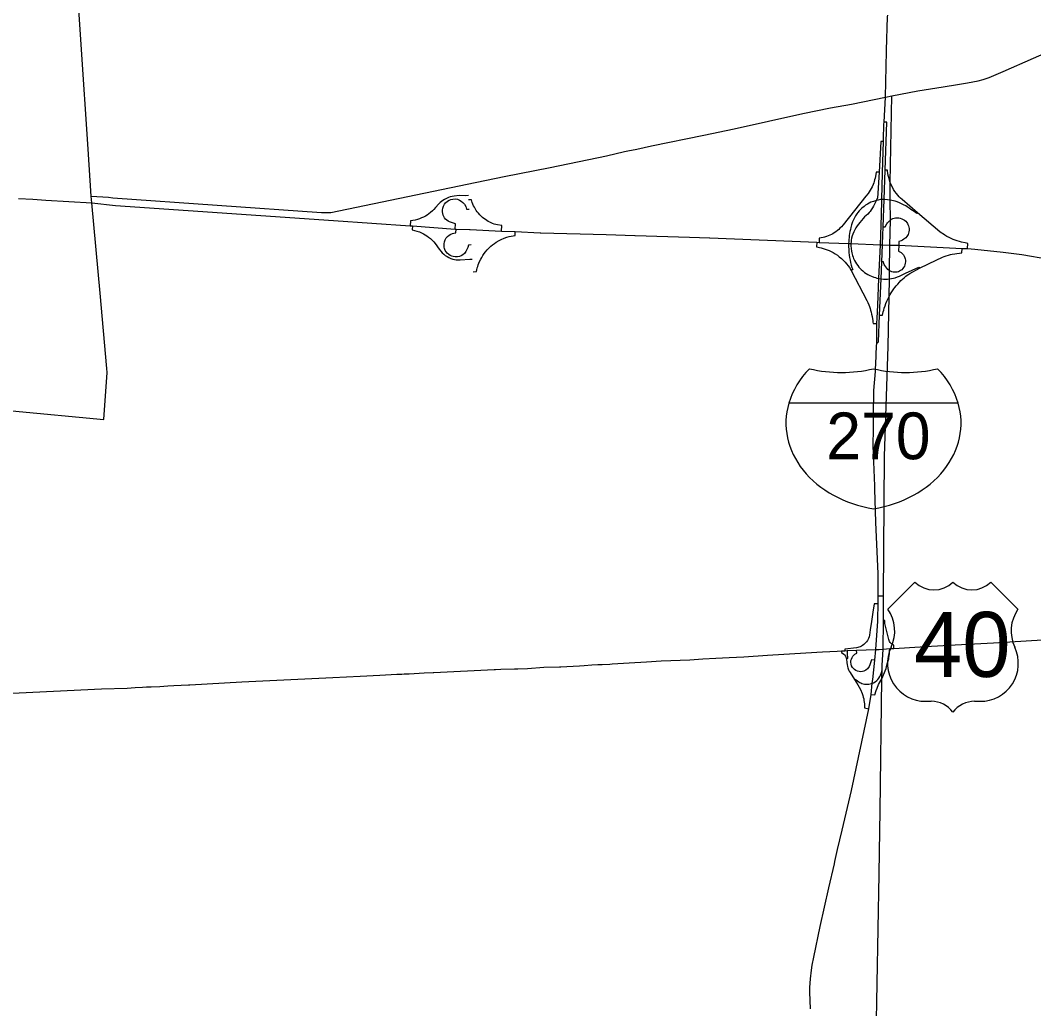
# Model space of a CAD drawing. Extents: x -1146 to -445, y -1283 to -822.
# Drawn here: x -1013.6 to -959.3, y -1085.1 to -1032.2 of the extents above; entities that cross this region are included whole.
import ezdxf

# ---------------------------------------------------------------- set-up
doc = ezdxf.new("R2010")
doc.units = 0
for name, color, linetype in [('GM_X_Interchange_Ramps', 7, 'Continuous'), ('GM_X_Interstate_Route', 7, 'Continuous'), ('GM_X_Interstate_Shield', 7, 'Continuous'), ('GM_X_Township', 7, 'Continuous'), ('GM_X_US_Route', 7, 'Continuous'), ('GM_X_US_Shield', 7, 'Continuous')]:
    doc.layers.add(name, color=color, linetype=linetype)

msp = doc.modelspace()

# ---------------------------------------------------------------- linework, layer by layer
at = {"layer": 'GM_X_Interchange_Ramps'}
for points in [[(-967.737, -1049.54), (-967.64, -1049.446), (-967.585, -1048.033), (-967.509, -1046.083), (-967.473, -1045.168), (-967.438, -1044.263), (-967.436, -1044.225), (-967.402, -1043.29), (-967.35, -1041.831), (-967.293, -1040.266), (-967.2, -1037.703), (-967.348, -1037.696)], [(-967.383, -1038.733), (-967.527, -1038.726), (-967.618, -1040.374), (-967.679, -1041.495), (-967.707, -1041.771), (-967.764, -1041.888), (-967.792, -1041.944), (-967.854, -1042.083), (-967.911, -1042.196), (-967.959, -1042.278), (-968.032, -1042.388), (-968.095, -1042.471), (-968.151, -1042.537), (-968.221, -1042.612), (-968.311, -1042.693), (-968.387, -1042.765), (-968.471, -1042.853), (-968.562, -1042.955), (-968.648, -1043.061), (-968.724, -1043.164), (-968.785, -1043.254), (-968.85, -1043.359), (-968.905, -1043.455), (-968.965, -1043.568), (-969.023, -1043.693), (-969.056, -1043.789), (-969.085, -1043.904), (-969.105, -1044.012), (-969.115, -1044.097), (-969.122, -1044.197), (-969.123, -1044.212), (-969.125, -1044.308), (-969.115, -1044.466), (-969.097, -1044.596), (-969.076, -1044.699), (-969.04, -1044.826), (-969.008, -1044.918), (-968.976, -1044.999), (-968.927, -1045.102), (-968.874, -1045.198), (-968.821, -1045.282), (-968.755, -1045.376), (-968.689, -1045.457), (-968.629, -1045.524), (-968.565, -1045.587), (-968.488, -1045.656), (-968.389, -1045.735), (-968.305, -1045.792), (-968.211, -1045.85), (-968.116, -1045.9), (-968.017, -1045.945), (-967.892, -1045.992), (-967.808, -1046.018), (-967.73, -1046.038), (-967.629, -1046.063), (-967.619, -1046.064), (-967.509, -1046.083), (-967.5, -1046.085), (-967.379, -1046.097), (-967.284, -1046.1), (-967.171, -1046.098), (-967.053, -1046.087), (-966.942, -1046.07), (-966.848, -1046.049), (-966.748, -1046.021), (-966.63, -1045.98), (-966.517, -1045.931), (-966.197, -1045.78), (-965.48, -1045.449), (-965.448, -1045.511)], [(-962.877, -1044.465), (-962.856, -1044.187), (-963.003, -1044.161), (-963.197, -1044.111), (-963.317, -1044.081), (-963.434, -1044.047), (-963.547, -1044.009), (-963.649, -1043.97), (-963.764, -1043.921), (-963.865, -1043.873), (-963.989, -1043.808), (-964.102, -1043.742), (-964.221, -1043.664), (-964.295, -1043.612), (-964.361, -1043.563), (-965.554, -1042.542), (-966.371, -1041.843), (-966.466, -1041.756), (-966.538, -1041.685), (-966.617, -1041.598), (-966.684, -1041.516), (-966.768, -1041.402), (-966.838, -1041.293), (-966.9, -1041.184), (-966.964, -1041.055), (-967.018, -1040.922), (-967.059, -1040.803), (-967.1, -1040.663), (-967.129, -1040.547), (-967.152, -1040.427), (-967.168, -1040.317), (-967.171, -1040.271), (-967.293, -1040.266)], [(-967.618, -1040.374), (-967.771, -1040.367), (-967.813, -1040.607), (-967.831, -1040.692), (-967.854, -1040.781), (-967.879, -1040.865), (-967.903, -1040.939), (-967.938, -1041.03), (-967.99, -1041.15), (-968.042, -1041.253), (-968.092, -1041.343), (-968.142, -1041.423), (-968.203, -1041.512), (-968.315, -1041.656), (-969.543, -1043.199), (-969.627, -1043.295), (-969.706, -1043.376), (-969.77, -1043.435), (-969.848, -1043.5), (-969.925, -1043.558), (-970.013, -1043.617), (-970.096, -1043.667), (-970.167, -1043.705), (-970.245, -1043.742), (-970.342, -1043.783), (-970.42, -1043.812), (-970.526, -1043.845), (-970.613, -1043.867), (-970.812, -1043.908), (-970.826, -1044.129)], [(-989.595, -1041.623), (-989.735, -1041.632), (-990.093, -1041.625), (-990.359, -1041.651), (-990.463, -1041.674), (-990.576, -1041.701), (-990.656, -1041.726), (-990.736, -1041.758), (-990.809, -1041.793), (-990.88, -1041.833), (-990.963, -1041.888), (-991.035, -1041.944), (-991.103, -1042.005), (-991.168, -1042.072), (-991.362, -1042.269), (-991.442, -1042.363), (-991.516, -1042.441), (-991.623, -1042.537), (-991.715, -1042.609), (-991.801, -1042.669), (-991.897, -1042.728), (-991.994, -1042.779), (-992.095, -1042.825), (-992.21, -1042.869), (-992.314, -1042.902), (-992.439, -1042.933), (-992.686, -1042.976), (-992.703, -1043.242)], [(-990.301, -1043.415), (-990.281, -1043.131), (-990.506, -1043.07), (-990.598, -1043.038), (-990.67, -1043.001), (-990.749, -1042.945), (-990.814, -1042.882), (-990.868, -1042.815), (-990.909, -1042.747), (-990.943, -1042.668), (-990.967, -1042.588), (-990.98, -1042.496), (-990.981, -1042.406), (-990.965, -1042.302), (-990.931, -1042.198), (-990.875, -1042.093), (-990.81, -1042.011), (-990.719, -1041.93), (-990.614, -1041.867), (-990.531, -1041.835), (-990.43, -1041.812), (-990.302, -1041.806), (-990.183, -1041.824), (-990.07, -1041.864), (-989.972, -1041.92), (-989.882, -1041.994), (-989.803, -1042.09), (-989.738, -1042.215), (-989.691, -1042.36), (-989.554, -1042.351)], [(-987.819, -1043.524), (-987.807, -1043.235), (-988.037, -1043.193), (-988.13, -1043.17), (-988.21, -1043.147), (-988.298, -1043.116), (-988.38, -1043.083), (-988.443, -1043.054), (-988.527, -1043.011), (-988.614, -1042.96), (-988.684, -1042.915), (-988.762, -1042.858), (-988.831, -1042.803), (-988.91, -1042.732), (-988.98, -1042.663), (-989.058, -1042.575), (-989.12, -1042.498), (-989.173, -1042.423), (-989.22, -1042.349), (-989.275, -1042.252), (-989.317, -1042.166), (-989.351, -1042.09), (-989.386, -1041.996), (-989.435, -1041.845), (-989.582, -1041.855)], [(-965.554, -1042.542), (-965.598, -1042.592), (-965.743, -1042.479), (-965.825, -1042.419), (-965.908, -1042.362), (-966.008, -1042.292), (-966.11, -1042.226), (-966.188, -1042.179), (-966.298, -1042.119), (-966.518, -1042.008), (-966.645, -1041.953), (-966.75, -1041.916), (-967.012, -1041.866), (-967.311, -1041.829), (-967.35, -1041.831), (-967.426, -1041.833), (-967.458, -1041.836), (-967.54, -1041.844), (-967.667, -1041.864), (-967.764, -1041.888), (-967.81, -1041.899), (-967.919, -1041.934), (-968.054, -1041.987), (-968.143, -1042.03), (-968.242, -1042.084), (-968.335, -1042.143), (-968.42, -1042.203), (-968.529, -1042.293), (-968.61, -1042.37), (-968.683, -1042.448), (-968.753, -1042.531), (-968.812, -1042.61), (-968.877, -1042.709), (-968.934, -1042.81), (-968.989, -1042.923), (-969.031, -1043.028), (-969.085, -1043.193), (-969.124, -1043.334), (-969.15, -1043.441), (-969.173, -1043.546), (-969.192, -1043.648), (-969.208, -1043.754), (-969.222, -1043.863), (-969.233, -1043.971), (-969.241, -1044.085), (-969.245, -1044.192), (-969.246, -1044.225), (-969.247, -1044.358), (-969.241, -1044.51), (-969.23, -1044.669), (-969.213, -1044.816), (-969.192, -1044.948), (-969.168, -1045.078), (-969.139, -1045.209), (-969.101, -1045.351), (-969.066, -1045.467), (-969.025, -1045.589), (-969.111, -1045.634)], [(-967.402, -1043.29), (-967.284, -1043.295), (-967.194, -1043.144), (-967.156, -1043.09), (-967.114, -1043.037), (-967.063, -1042.984), (-967.005, -1042.936), (-966.943, -1042.897), (-966.87, -1042.861), (-966.806, -1042.84), (-966.73, -1042.823), (-966.645, -1042.816), (-966.562, -1042.82), (-966.484, -1042.835), (-966.389, -1042.866), (-966.317, -1042.903), (-966.256, -1042.944), (-966.188, -1043.003), (-966.127, -1043.075), (-966.099, -1043.117), (-966.067, -1043.177), (-966.039, -1043.249), (-966.021, -1043.317), (-966.01, -1043.393), (-966.008, -1043.471), (-966.018, -1043.559), (-966.04, -1043.641), (-966.065, -1043.707), (-966.098, -1043.768), (-966.133, -1043.82), (-966.185, -1043.879), (-966.24, -1043.928), (-966.293, -1043.967), (-966.355, -1044.005), (-966.434, -1044.043), (-966.549, -1044.085), (-966.557, -1044.286)], [(-992.584, -1043.249), (-992.597, -1043.456), (-992.35, -1043.523), (-992.216, -1043.569), (-992.096, -1043.62), (-991.993, -1043.671), (-991.898, -1043.725), (-991.809, -1043.783), (-991.72, -1043.848), (-991.626, -1043.924), (-991.529, -1044.015), (-991.45, -1044.098), (-991.377, -1044.185), (-991.153, -1044.485), (-991.076, -1044.595), (-990.999, -1044.683), (-990.912, -1044.767), (-990.828, -1044.834), (-990.738, -1044.893), (-990.636, -1044.948), (-990.527, -1044.995), (-990.429, -1045.026), (-990.34, -1045.048), (-990.253, -1045.062), (-990.141, -1045.071), (-990.034, -1045.071), (-989.511, -1045.038), (-989.385, -1045.032)], [(-989.44, -1044.27), (-989.593, -1044.275), (-989.632, -1044.398), (-989.669, -1044.515), (-989.724, -1044.619), (-989.805, -1044.719), (-989.892, -1044.791), (-989.979, -1044.843), (-990.067, -1044.878), (-990.177, -1044.902), (-990.296, -1044.906), (-990.4, -1044.891), (-990.483, -1044.866), (-990.575, -1044.824), (-990.645, -1044.777), (-990.721, -1044.71), (-990.777, -1044.642), (-990.828, -1044.56), (-990.868, -1044.464), (-990.888, -1044.384), (-990.898, -1044.298), (-990.896, -1044.205), (-990.877, -1044.099), (-990.837, -1043.993), (-990.778, -1043.892), (-990.713, -1043.815), (-990.63, -1043.745), (-990.529, -1043.686), (-990.448, -1043.655), (-990.364, -1043.635), (-990.267, -1043.627), (-990.253, -1043.418)], [(-989.33, -1045.702), (-989.164, -1045.694), (-989.143, -1045.598), (-989.116, -1045.495), (-989.094, -1045.415), (-989.064, -1045.329), (-989.034, -1045.249), (-988.997, -1045.162), (-988.936, -1045.035), (-988.879, -1044.933), (-988.822, -1044.84), (-988.749, -1044.733), (-988.673, -1044.634), (-988.585, -1044.531), (-988.492, -1044.434), (-988.386, -1044.335), (-988.3, -1044.263), (-988.201, -1044.189), (-988.099, -1044.12), (-987.954, -1044.034), (-987.831, -1043.972), (-987.681, -1043.908), (-987.54, -1043.858), (-987.412, -1043.821), (-987.298, -1043.793), (-987.098, -1043.756), (-987.09, -1043.547)], [(-970.951, -1044.124), (-970.966, -1044.371), (-970.72, -1044.423), (-970.601, -1044.455), (-970.493, -1044.489), (-970.39, -1044.527), (-970.287, -1044.57), (-970.18, -1044.621), (-970.067, -1044.681), (-969.96, -1044.745), (-969.847, -1044.821), (-969.742, -1044.899), (-969.628, -1044.995), (-969.518, -1045.099), (-969.426, -1045.197), (-969.353, -1045.282), (-969.276, -1045.38), (-969.205, -1045.481), (-969.111, -1045.634), (-968.261, -1047.247), (-968.214, -1047.351), (-968.167, -1047.465), (-968.131, -1047.563), (-968.095, -1047.668), (-968.066, -1047.766), (-968.038, -1047.868), (-968.012, -1047.972), (-967.988, -1048.09), (-967.966, -1048.217), (-967.953, -1048.317), (-967.943, -1048.4), (-967.938, -1048.465), (-967.736, -1048.464)], [(-967.585, -1048.033), (-967.431, -1048.032), (-967.39, -1047.848), (-967.364, -1047.75), (-967.335, -1047.648), (-967.296, -1047.528), (-967.248, -1047.399), (-967.194, -1047.269), (-967.135, -1047.14), (-967.081, -1047.035), (-967.02, -1046.924), (-966.959, -1046.823), (-966.895, -1046.724), (-966.827, -1046.625), (-966.764, -1046.541), (-966.701, -1046.461), (-966.616, -1046.36), (-966.529, -1046.266), (-966.443, -1046.178), (-966.359, -1046.098), (-966.274, -1046.021), (-966.185, -1045.947), (-966.111, -1045.889), (-966.029, -1045.828), (-965.974, -1045.79), (-965.448, -1045.511), (-964.529, -1045.07), (-964.458, -1045.033), (-964.333, -1044.973), (-964.221, -1044.925), (-964.133, -1044.891), (-964.019, -1044.85), (-963.904, -1044.814), (-963.797, -1044.785), (-963.699, -1044.762), (-963.564, -1044.735), (-963.448, -1044.717), (-963.31, -1044.701), (-963.18, -1044.69), (-963.162, -1044.451)], [(-966.557, -1044.286), (-966.568, -1044.603), (-966.506, -1044.632), (-966.439, -1044.676), (-966.375, -1044.732), (-966.315, -1044.802), (-966.27, -1044.875), (-966.236, -1044.953), (-966.218, -1045.017), (-966.205, -1045.091), (-966.202, -1045.164), (-966.209, -1045.243), (-966.23, -1045.331), (-966.258, -1045.405), (-966.298, -1045.476), (-966.338, -1045.531), (-966.403, -1045.598), (-966.459, -1045.642), (-966.515, -1045.677), (-966.579, -1045.706), (-966.65, -1045.725), (-966.758, -1045.732), (-966.854, -1045.722), (-966.938, -1045.7), (-967.005, -1045.672), (-967.051, -1045.645), (-967.076, -1045.631), (-967.139, -1045.581), (-967.205, -1045.511), (-967.258, -1045.443), (-967.306, -1045.373), (-967.34, -1045.309), (-967.359, -1045.259), (-967.383, -1045.171), (-967.473, -1045.168)], [(-968.927, -1067.526), (-968.887, -1067.5), (-968.767, -1067.605), (-968.703, -1067.651), (-968.647, -1067.683), (-968.585, -1067.713), (-968.533, -1067.733), (-968.467, -1067.753), (-968.392, -1067.768), (-968.306, -1067.777), (-968.227, -1067.776), (-968.157, -1067.769), (-968.087, -1067.756), (-968.015, -1067.735), (-967.975, -1067.719), (-967.92, -1067.696), (-967.828, -1067.643), (-967.742, -1067.577), (-967.681, -1067.518), (-967.624, -1067.447), (-967.571, -1067.365), (-967.535, -1067.289), (-967.504, -1067.202), (-967.455, -1067.032), (-967.445, -1066.771), (-967.39, -1065.897), (-967.373, -1064.361), (-967.386, -1063.071), (-967.654, -1063.061)], [(-967.665, -1063.482), (-967.873, -1063.475), (-967.943, -1063.918), (-968.017, -1064.413), (-968.088, -1064.869), (-968.129, -1065.156), (-968.152, -1065.247), (-968.183, -1065.334), (-968.236, -1065.436), (-968.285, -1065.509), (-968.354, -1065.59), (-968.422, -1065.652), (-968.496, -1065.706), (-968.556, -1065.742), (-968.623, -1065.775), (-968.822, -1065.839), (-969.443, -1065.898), (-969.441, -1065.985)], [(-966.822, -1065.858), (-966.833, -1065.689), (-966.894, -1065.66), (-966.958, -1065.613), (-967.015, -1065.551), (-967.056, -1065.488), (-967.077, -1065.442), (-967.095, -1065.382), (-967.299, -1064.522), (-967.312, -1064.417), (-967.313, -1064.36), (-967.373, -1064.361)], [(-969.625, -1065.992), (-969.62, -1066.081), (-969.499, -1066.17), (-969.456, -1066.214), (-969.415, -1066.27), (-969.386, -1066.325), (-969.37, -1066.368), (-969.356, -1066.417), (-969.338, -1066.629), (-969.329, -1066.717), (-969.307, -1066.825), (-969.283, -1066.907), (-969.243, -1067.009), (-969.208, -1067.08), (-969.163, -1067.155), (-968.927, -1067.526), (-968.751, -1067.813), (-968.614, -1068.069), (-968.522, -1068.284), (-968.489, -1068.378), (-968.46, -1068.475), (-968.438, -1068.566), (-968.423, -1068.65), (-968.411, -1068.74), (-968.403, -1068.828), (-968.399, -1068.907), (-968.399, -1069.038), (-968.162, -1069.088)], [(-969.323, -1065.981), (-969.315, -1066.116), (-969.312, -1066.407), (-969.356, -1066.417)], [(-967.833, -1066.483), (-968.028, -1066.471), (-968.112, -1066.741), (-968.152, -1066.837), (-968.238, -1066.954), (-968.331, -1067.029), (-968.422, -1067.075), (-968.502, -1067.098), (-968.603, -1067.109), (-968.688, -1067.102), (-968.773, -1067.081), (-968.858, -1067.043), (-968.926, -1066.998), (-968.985, -1066.943), (-969.037, -1066.877), (-969.082, -1066.794), (-969.11, -1066.71), (-969.123, -1066.601), (-969.117, -1066.514), (-969.097, -1066.43), (-969.063, -1066.349), (-969.016, -1066.277), (-968.966, -1066.221), (-968.906, -1066.171), (-968.834, -1066.128), (-968.811, -1066.119), (-968.815, -1065.962)], [(-968.043, -1068.321), (-967.839, -1068.353), (-967.766, -1068.109), (-967.721, -1067.981), (-967.636, -1067.789), (-967.471, -1067.484), (-967.236, -1066.937), (-967.195, -1066.754), (-967.16, -1066.635), (-967.132, -1066.521), (-967.1, -1066.414), (-967.088, -1066.354), (-967.068, -1066.27), (-967.062, -1066.134), (-967.048, -1066.014), (-967.04, -1065.874)]]:
    msp.add_lwpolyline(points, dxfattribs=at)
at = {"layer": 'GM_X_Interstate_Route'}
for points in [[(-967.216, -1033.837), (-967.155, -1032.067), (-967.152, -1031.977)], [(-967.266, -1036.362), (-967.218, -1033.903), (-967.216, -1033.837)], [(-967.352, -1037.811), (-967.348, -1037.696), (-967.266, -1036.362)], [(-967.379, -1038.618), (-967.352, -1037.811)], [(-967.429, -1040.444), (-967.428, -1040.397), (-967.383, -1038.733), (-967.379, -1038.618)], [(-967.443, -1041.102), (-967.429, -1040.444)], [(-967.486, -1042.681), (-967.458, -1041.872), (-967.458, -1041.836), (-967.443, -1041.102)], [(-1013.666, -1041.775), (-1012.91, -1041.822), (-1012.206, -1041.866)], [(-1012.206, -1041.866), (-1009.745, -1042.021), (-1008.48, -1042.148), (-996.816, -1042.957)], [(-996.816, -1042.957), (-992.703, -1043.242), (-992.584, -1043.249), (-990.301, -1043.415), (-990.253, -1043.418), (-989.537, -1043.434)], [(-967.541, -1044.26), (-967.486, -1042.681)], [(-989.537, -1043.434), (-989.491, -1043.435), (-987.819, -1043.524), (-987.09, -1043.547), (-985.757, -1043.614)], [(-985.757, -1043.614), (-985.712, -1043.616), (-982.216, -1043.703), (-980.687, -1043.756)], [(-980.687, -1043.756), (-980.661, -1043.757), (-977.764, -1043.859), (-976.686, -1043.894)], [(-976.686, -1043.894), (-976.674, -1043.894), (-970.951, -1044.124), (-970.826, -1044.129), (-969.245, -1044.192), (-969.122, -1044.197), (-967.541, -1044.26)], [(-967.688, -1047.483), (-967.619, -1046.064), (-967.541, -1044.26)], [(-967.541, -1044.26), (-967.438, -1044.263), (-967.047, -1044.273), (-966.68, -1044.283)], [(-966.68, -1044.283), (-966.557, -1044.286), (-963.162, -1044.451), (-962.877, -1044.465), (-962.489, -1044.502)], [(-962.489, -1044.502), (-960.968, -1044.647), (-959.976, -1044.785), (-958.533, -1045.024), (-958.498, -1045.03)], [(-967.722, -1048.184), (-967.688, -1047.483)], [(-967.736, -1048.787), (-967.736, -1048.464), (-967.722, -1048.184)], [(-967.737, -1049.325), (-967.736, -1048.787)], [(-967.743, -1049.674), (-967.737, -1049.54), (-967.737, -1049.325)], [(-967.804, -1050.878), (-967.791, -1050.65), (-967.743, -1049.674)], [(-967.919, -1054.09), (-967.918, -1054.015), (-967.915, -1053.33), (-967.894, -1052.067), (-967.813, -1051.04), (-967.804, -1050.878)], [(-967.844, -1057.304), (-967.849, -1057.166), (-967.924, -1055.015), (-967.919, -1054.09)], [(-967.655, -1062.257), (-967.656, -1061.87), (-967.793, -1059.107), (-967.843, -1057.337), (-967.844, -1057.304)], [(-967.665, -1063.482), (-967.654, -1063.061), (-967.655, -1062.257)], [(-967.685, -1064.297), (-967.665, -1063.482)], [(-967.781, -1065.924), (-967.687, -1064.406), (-967.685, -1064.297)], [(-967.953, -1067.533), (-967.833, -1066.483), (-967.781, -1065.924)], [(-969.723, -1076.115), (-969.597, -1075.581), (-969.09, -1073.472), (-968.162, -1069.088), (-968.043, -1068.321), (-967.975, -1067.719), (-967.953, -1067.533)], [(-969.976, -1077.266), (-969.841, -1076.62), (-969.723, -1076.115)], [(-970.296, -1078.676), (-970.002, -1077.394), (-969.976, -1077.266)], [(-971.293, -1085.147), (-971.322, -1084.268), (-971.313, -1084.017), (-971.282, -1083.547), (-971.236, -1083.085), (-971.198, -1082.808), (-971.113, -1082.385), (-970.77, -1080.748), (-970.296, -1078.676)]]:
    msp.add_lwpolyline(points, dxfattribs=at)
at = {"layer": 'GM_X_Interstate_Shield'}
msp.add_line((-963.381, -1052.728), (-972.446, -1052.728), dxfattribs=at)
msp.add_line((-963.381, -1052.728), (-972.446, -1052.728), dxfattribs=at)
for centre, start_param, end_param in [((-966.741, -1053.8), 2.47259, 2.911027), ((-969.625, -1046.409), 4.415841, 5.008937), ((-966.201, -1046.409), 4.415841, 5.008937), ((-969.085, -1053.8), 0.230566, 0.669003), ((-966.741, -1053.8), 2.911027, 4.511031), ((-969.085, -1053.8), 4.913747, 6.513751)]:
    msp.add_ellipse(centre, major_axis=(5.859, 0), ratio=0.8, start_param=start_param, end_param=end_param, dxfattribs=at)
at = {"layer": 'GM_X_Township'}
for points in [[(-1009.776, -1041.652), (-1009.942, -1039.137), (-1010.312, -1033.534), (-1010.827, -1025.755), (-1011.143, -1022.204), (-1011.463, -1020.087), (-1012.848, -1007.56), (-1013.063, -1005.635), (-1013.224, -1004.12), (-1013.486, -1001.672)], [(-967.767, -1086.722), (-967.605, -1077.953), (-967.591, -1076.751), (-967.563, -1074.56), (-967.471, -1067.484), (-967.455, -1067.032), (-967.445, -1066.771), (-967.39, -1065.897), (-967.373, -1064.361), (-967.386, -1063.071), (-967.317, -1055.599), (-967.123, -1049.679), (-967.081, -1047.035), (-967.053, -1046.087), (-967.051, -1045.645), (-967.047, -1044.273), (-967.005, -1042.936), (-967.012, -1041.867), (-967.018, -1040.923), (-966.936, -1036.293), (-965.542, -1036.027), (-964.176, -1035.802), (-963.416, -1035.684), (-962.889, -1035.6), (-962.315, -1035.491), (-962.038, -1035.413), (-961.715, -1035.301), (-960.972, -1034.98), (-959.353, -1034.273), (-955.306, -1032.509)], [(-1014.013, -1053.141), (-1009.102, -1053.617), (-1008.928, -1051.091), (-1008.941, -1050.873), (-1009.307, -1046.85), (-1009.745, -1042.021), (-1009.776, -1041.652), (-1008.86, -1041.707), (-1008.625, -1041.743), (-997.463, -1042.533), (-996.959, -1042.526), (-989.657, -1041.01), (-987.682, -1040.609), (-985.221, -1040.122), (-982.207, -1039.497), (-981.246, -1039.261), (-981.058, -1039.226), (-980.58, -1039.138), (-979.789, -1038.971), (-976.987, -1038.389), (-975.378, -1038.047), (-971.69, -1037.238), (-970.21, -1036.923), (-969.081, -1036.725), (-967.266, -1036.362), (-966.936, -1036.293)]]:
    msp.add_lwpolyline(points, dxfattribs=at)
at = {"layer": 'GM_X_US_Route'}
for points in [[(-966.822, -1065.858), (-966.822, -1065.858), (-965.419, -1065.78)], [(-965.419, -1065.78), (-963.876, -1065.694)], [(-963.876, -1065.694), (-961.49, -1065.562)], [(-961.49, -1065.562), (-957.999, -1065.341)], [(-980.988, -1066.634), (-980.07, -1066.576), (-979.276, -1066.528), (-977.74, -1066.47), (-977.046, -1066.42), (-976.342, -1066.392), (-975.644, -1066.352), (-974.851, -1066.31), (-973.577, -1066.232)], [(-973.577, -1066.232), (-970.943, -1066.07), (-970.644, -1066.054)], [(-970.644, -1066.054), (-969.85, -1066.012), (-969.625, -1065.992)], [(-969.625, -1065.992), (-969.441, -1065.985), (-969.323, -1065.981), (-968.815, -1065.962), (-967.781, -1065.924)], [(-967.781, -1065.924), (-967.616, -1065.913)], [(-967.616, -1065.913), (-967.39, -1065.897), (-967.04, -1065.874)], [(-967.04, -1065.874), (-966.822, -1065.858)], [(-987.088, -1066.955), (-986.956, -1066.952), (-986.422, -1066.938), (-985.547, -1066.873), (-984.709, -1066.842), (-984.65, -1066.84), (-984.328, -1066.827), (-983.638, -1066.788), (-983.395, -1066.773), (-982.99, -1066.748), (-982.66, -1066.729), (-982.431, -1066.718)], [(-982.431, -1066.718), (-982.032, -1066.7), (-981.901, -1066.691)], [(-981.901, -1066.691), (-980.988, -1066.634)], [(-1001.711, -1067.65), (-996.84, -1067.416)], [(-996.84, -1067.416), (-995.392, -1067.347)], [(-995.392, -1067.347), (-994.339, -1067.297), (-993.417, -1067.249)], [(-993.417, -1067.249), (-993.154, -1067.235)], [(-993.154, -1067.235), (-993.022, -1067.229)], [(-993.022, -1067.229), (-992.828, -1067.219), (-992.759, -1067.215)], [(-992.759, -1067.215), (-991.969, -1067.174)], [(-991.969, -1067.174), (-991.473, -1067.15), (-991.441, -1067.148)], [(-991.441, -1067.148), (-988.21, -1066.987), (-988.144, -1066.983)], [(-988.144, -1066.983), (-987.864, -1066.969), (-987.124, -1066.956), (-987.088, -1066.955)], [(-1009.235, -1068.021), (-1007.857, -1067.988), (-1007.432, -1067.957)], [(-1007.432, -1067.957), (-1007.028, -1067.935), (-1006.823, -1067.925)], [(-1006.823, -1067.925), (-1006.564, -1067.913), (-1006.098, -1067.893), (-1005.67, -1067.867), (-1005.354, -1067.853), (-1004.579, -1067.815), (-1004.51, -1067.811)], [(-1004.51, -1067.811), (-1001.711, -1067.65)], [(-1043.371, -1069.665), (-1036.862, -1069.334), (-1028.965, -1068.995), (-1026.028, -1068.832), (-1025.848, -1068.833), (-1023.012, -1068.7), (-1021.174, -1068.604), (-1019.911, -1068.543), (-1014.37, -1068.275), (-1009.235, -1068.021)]]:
    msp.add_lwpolyline(points, dxfattribs=at)
at = {"layer": 'GM_X_US_Shield'}
for p, q in [((-965.692, -1062.313), (-967.142, -1063.763)), ((-960.181, -1063.763), (-961.631, -1062.313)), ((-965.112, -1068.694), (-964.822, -1068.694)), ((-962.501, -1068.694), (-962.211, -1068.694))]:
    msp.add_line(p, q, dxfattribs=at)
for centre, radius, start, end in [((-964.677, -1061.277), 1.45, 225.573, 314.427), ((-962.646, -1061.277), 1.45, 225.573, 314.427), ((-968.805, -1064.927), 2.03, 334.5471, 35.0009), ((-958.518, -1064.927), 2.03, 144.9991, 205.4529), ((-965.134, -1066.663), 2.03, 154.8319, 270.6383), ((-962.189, -1066.663), 2.03, 269.3617, 25.1681), ((-964.822, -1070.144), 1.45, 36.8699, 90), ((-962.501, -1070.144), 1.45, 90, 143.1301)]:
    msp.add_arc(centre, radius, start, end, dxfattribs=at)

# ---------------------------------------------------------------- texts
at = {"layer": 'GM_X_Interstate_Shield'}
msp.add_text('270', height=2.5, dxfattribs=at).set_placement((-970.438, -1055.736))
at = {"layer": 'GM_X_US_Shield'}
msp.add_text('40', height=3.4805, dxfattribs=at).set_placement((-965.752, -1067.388))

doc.saveas('drawing.dxf')
